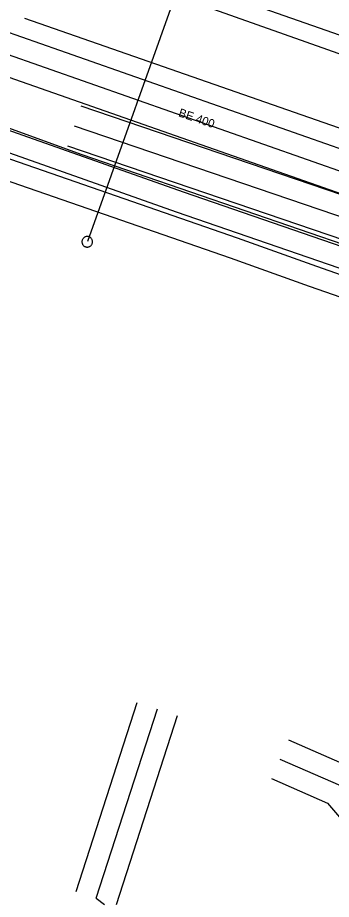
# Model space of a CAD drawing. Extents: x -762993 to -761845, y -975230 to -974501.
# Drawn here: x -762374.19 to -762359.36, y -975003.77 to -974962.16 of the extents above; entities that cross this region are included whole.
import ezdxf

# ---------------------------------------------------------------- set-up
doc = ezdxf.new("R2010")
doc.units = 0
for name, color, linetype in [('IS_CETIN_OP', 7, 'Continuous'), ('IS_CETIN_podzem metalika zam', 7, 'Continuous'), ('IS_CETIN_podzem NN', 7, 'Continuous'), ('IS_CETIN_podzem optika zam', 7, 'Continuous'), ('IS_CETIN_podzem out of order', 7, 'Continuous'), ('IS_CEZ-D_el vedeni NN podzem', 7, 'Continuous'), ('IS_CEZ-D_el vedeni VN podzem', 7, 'Continuous'), ('IS_CEZ-D_OP', 7, 'Continuous'), ('IS_DPmUL_OP', 7, 'Continuous'), ('IS_DPmUL_VO vedeni podzem', 7, 'Continuous'), ('IS_GASNET_plyn NTL rad', 7, 'Continuous'), ('IS_GASNET_plyn OP', 7, 'Continuous'), ('IS_SCVK_kanalizace anotace', 7, 'Continuous'), ('IS_SCVK_kanalizace jednotna', 7, 'Continuous'), ('IS_SCVK_vodovod OP', 7, 'Continuous'), ('IS_SCVK_vodovod pripojky', 7, 'Continuous'), ('IS_SCVK_vodovod znaky', 7, 'Continuous')]:
    doc.layers.add(name, color=color, linetype=linetype)

msp = doc.modelspace()

# ---------------------------------------------------------------- linework, layer by layer
at = {"layer": 'IS_CETIN_OP'}
for points in [[(-762361.39, -974996.234), (-762358.32, -974997.575), (-762355.772, -975000.548), (-762352.371, -975001.073), (-762342.707, -974993.089)], [(-762371.421, -975003.402), (-762368.531, -974994.472)], [(-762369.519, -975004.018), (-762366.629, -974995.088)], [(-762362.19, -974998.066), (-762359.54, -974999.225), (-762356.808, -975002.412), (-762351.789, -975003.187), (-762342.909, -974995.85)]]:
    msp.add_lwpolyline(points, dxfattribs=at)
at = {"layer": 'IS_CETIN_podzem metalika zam'}
msp.add_lwpolyline([(-762370.47, -975003.71), (-762367.58, -974994.78)], dxfattribs=at)
at = {"layer": 'IS_CETIN_podzem NN'}
msp.add_lwpolyline([(-762361.79, -974997.15), (-762358.93, -974998.4), (-762356.29, -975001.48), (-762352.08, -975002.13), (-762342.07, -974993.86)], dxfattribs=at)
at = {"layer": 'IS_CETIN_podzem optika zam'}
msp.add_lwpolyline([(-762361.79, -974997.15), (-762358.93, -974998.4), (-762356.29, -975001.48), (-762352.08, -975002.13), (-762342.07, -974993.86)], dxfattribs=at)
at = {"layer": 'IS_CETIN_podzem out of order'}
for points in [[(-762377.04, -974956.66), (-762339.91, -974969.63), (-762327.23, -974974.06)], [(-762393.36, -974970.49), (-762394.76, -974970.05), (-762391.76, -974961.27), (-762386.9, -974962.9), (-762371.15, -974968.61), (-762342.91, -974978.3), (-762324.01, -974984.93), (-762322.43, -974985.48)], [(-762370.47, -975003.71), (-762370.08, -975004.01)]]:
    msp.add_lwpolyline(points, dxfattribs=at)
at = {"layer": 'IS_CEZ-D_el vedeni NN podzem'}
msp.add_lwpolyline([(-762394.922, -974961.348), (-762366.691, -974971.325), (-762338.912, -974980.87), (-762333.235, -974982.66), (-762317.369, -974988.815), (-762313.901, -974990.502), (-762312.492, -974990.931), (-762308.55, -974979.749), (-762308.284, -974978.995), (-762308.259, -974979.004), (-762304.782, -974980.906), (-762293.136, -974984.559), (-762291.208, -974984.727), (-762288.899, -974984.279), (-762285.346, -974981.506), (-762284.881, -974980.325), (-762284.547, -974977.953), (-762290.432, -974954.683), (-762291.314, -974953.684), (-762291.816, -974954.174), (-762292.054, -974954.011)], dxfattribs=at)
at = {"layer": 'IS_CEZ-D_el vedeni VN podzem'}
msp.add_lwpolyline([(-762322.36, -974987.09), (-762324.59, -974986.24), (-762328.28, -974985.04), (-762360.05, -974973.9), (-762363.79, -974972.56), (-762395.59, -974961.56), (-762398.7, -974960.48), (-762421.28, -974952.57), (-762425.16, -974951.24), (-762434.97, -974947.57)], dxfattribs=at)
at = {"layer": 'IS_CEZ-D_OP'}
for points in [[(-762356.318, -974976.268), (-762360.384, -974974.843), (-762364.122, -974973.503), (-762395.917, -974962.505), (-762399.029, -974961.424), (-762421.607, -974953.515), (-762425.497, -974952.181), (-762435.253, -974948.532)], [(-762425.326, -974953.474), (-762425.823, -974952.392), (-762424.284, -974951.508), (-762423.951, -974951.317), (-762421.468, -974950.868), (-762394.588, -974960.405), (-762366.362, -974970.381), (-762338.599, -974979.92), (-762332.903, -974981.716), (-762317.463, -974987.706)]]:
    msp.add_lwpolyline(points, dxfattribs=at)
at = {"layer": 'IS_DPmUL_OP'}
for points in [[(-762371.192, -974966.319), (-762342.187, -974976.181)], [(-762371.836, -974968.213), (-762342.831, -974978.075)]]:
    msp.add_lwpolyline(points, dxfattribs=at)
at = {"layer": 'IS_DPmUL_VO vedeni podzem'}
msp.add_lwpolyline([(-762371.514, -974967.266), (-762342.509, -974977.128)], dxfattribs=at)
at = {"layer": 'IS_GASNET_plyn NTL rad'}
msp.add_lwpolyline([(-762416.145, -974949.855), (-762381.041, -974961.735), (-762378.19, -974962.7), (-762377.47, -974962.93), (-762377.29, -974962.99), (-762377.092, -974963.051), (-762377.03, -974963.07), (-762356.37, -974970.3), (-762354.158, -974971.062), (-762353.96, -974971.13), (-762350.61, -974972.23), (-762350.171, -974972.416), (-762350.02, -974972.48), (-762336.17, -974977.35), (-762335.29, -974977.64), (-762335.11, -974977.68), (-762305.627, -974988.849), (-762305.14, -974989.03), (-762304.73, -974989.2), (-762303.75, -974989.6), (-762303.207, -974990.005), (-762302.681, -974990.396), (-762302.34, -974990.65)], dxfattribs=at)
at = {"layer": 'IS_GASNET_plyn OP'}
for points in [[(-762376.718, -974962.12), (-762356.042, -974969.355), (-762353.833, -974970.116), (-762353.642, -974970.182), (-762350.258, -974971.293), (-762349.781, -974971.495), (-762349.659, -974971.547), (-762335.848, -974976.403), (-762335.024, -974976.675), (-762334.823, -974976.719), (-762305.276, -974987.913)], [(-762305.978, -974989.785), (-762335.397, -974978.641), (-762335.556, -974978.605), (-762336.492, -974978.297), (-762350.381, -974973.413), (-762350.561, -974973.337), (-762350.962, -974973.167), (-762354.278, -974972.078), (-762354.483, -974972.008), (-762356.698, -974971.245), (-762377.342, -974964.02)]]:
    msp.add_lwpolyline(points, dxfattribs=at)
at = {"layer": 'IS_SCVK_kanalizace jednotna'}
msp.add_lwpolyline([(-762373.865, -974962.18), (-762330.791, -974977.171)], dxfattribs=at)
at = {"layer": 'IS_SCVK_vodovod OP'}
msp.add_lwpolyline([(-762371.852, -974959.319), (-762366.733, -974961.125), (-762365.959, -974961.392), (-762351.074, -974966.651), (-762348.097, -974967.643), (-762328.082, -974974.681), (-762324.702, -974975.757), (-762322.277, -974976.604), (-762303.577, -974983.171), (-762292.841, -974986.577), (-762286.645, -974987.706), (-762284.209, -974987.979), (-762282.49, -974987.47)], dxfattribs=at)
at = {"layer": 'IS_SCVK_vodovod pripojky'}
msp.add_lwpolyline([(-762366.338, -974959.969), (-762370.882, -974972.729)], dxfattribs=at)
at = {"layer": 'IS_SCVK_vodovod znaky'}
for points in [[(-762371.145, -974972.707), (-762371.147, -974972.733)], [(-762371.145, -974972.707), (-762371.147, -974972.733)], [(-762371.147, -974972.733), (-762371.145, -974972.758)], [(-762371.147, -974972.733), (-762371.145, -974972.758)], [(-762371.145, -974972.758), (-762371.142, -974972.784)], [(-762371.145, -974972.758), (-762371.142, -974972.784)], [(-762371.14, -974972.681), (-762371.145, -974972.707)], [(-762371.14, -974972.681), (-762371.145, -974972.707)], [(-762371.142, -974972.784), (-762371.135, -974972.81)], [(-762371.142, -974972.784), (-762371.135, -974972.81)], [(-762371.133, -974972.655), (-762371.14, -974972.681)], [(-762371.133, -974972.655), (-762371.14, -974972.681)], [(-762371.135, -974972.81), (-762371.126, -974972.834)], [(-762371.135, -974972.81), (-762371.126, -974972.834)], [(-762371.123, -974972.632), (-762371.133, -974972.655)], [(-762371.123, -974972.632), (-762371.133, -974972.655)], [(-762371.126, -974972.834), (-762371.115, -974972.858)], [(-762371.126, -974972.834), (-762371.115, -974972.858)], [(-762371.111, -974972.608), (-762371.123, -974972.632)], [(-762371.111, -974972.608), (-762371.123, -974972.632)], [(-762371.115, -974972.858), (-762371.101, -974972.88)], [(-762371.115, -974972.858), (-762371.101, -974972.88)], [(-762371.096, -974972.586), (-762371.111, -974972.608)], [(-762371.096, -974972.586), (-762371.111, -974972.608)], [(-762371.101, -974972.88), (-762371.084, -974972.9)], [(-762371.101, -974972.88), (-762371.084, -974972.9)], [(-762371.08, -974972.567), (-762371.096, -974972.586)], [(-762371.08, -974972.567), (-762371.096, -974972.586)], [(-762371.062, -974972.548), (-762371.08, -974972.567)], [(-762371.062, -974972.548), (-762371.08, -974972.567)], [(-762371.042, -974972.532), (-762371.062, -974972.548)], [(-762371.042, -974972.532), (-762371.062, -974972.548)], [(-762371.019, -974972.518), (-762371.042, -974972.532)], [(-762371.019, -974972.518), (-762371.042, -974972.532)], [(-762370.996, -974972.506), (-762371.019, -974972.518)], [(-762370.996, -974972.506), (-762371.019, -974972.518)], [(-762370.971, -974972.498), (-762370.996, -974972.506)], [(-762370.971, -974972.498), (-762370.996, -974972.506)], [(-762370.945, -974972.49), (-762370.971, -974972.498)], [(-762370.945, -974972.49), (-762370.971, -974972.498)], [(-762370.919, -974972.486), (-762370.945, -974972.49)], [(-762370.919, -974972.486), (-762370.945, -974972.49)], [(-762370.894, -974972.486), (-762370.919, -974972.486)], [(-762370.894, -974972.486), (-762370.919, -974972.486)], [(-762370.867, -974972.488), (-762370.894, -974972.486)], [(-762370.867, -974972.488), (-762370.894, -974972.486)], [(-762370.842, -974972.492), (-762370.867, -974972.488)], [(-762370.842, -974972.492), (-762370.867, -974972.488)], [(-762370.816, -974972.499), (-762370.842, -974972.492)], [(-762370.816, -974972.499), (-762370.842, -974972.492)], [(-762370.792, -974972.509), (-762370.816, -974972.499)], [(-762370.792, -974972.509), (-762370.816, -974972.499)], [(-762370.769, -974972.521), (-762370.792, -974972.509)], [(-762370.769, -974972.521), (-762370.792, -974972.509)], [(-762370.748, -974972.535), (-762370.769, -974972.521)], [(-762370.748, -974972.535), (-762370.769, -974972.521)], [(-762370.727, -974972.552), (-762370.748, -974972.535)], [(-762370.727, -974972.552), (-762370.748, -974972.535)], [(-762370.709, -974972.571), (-762370.727, -974972.552)], [(-762370.709, -974972.571), (-762370.727, -974972.552)], [(-762370.693, -974972.592), (-762370.709, -974972.571)], [(-762370.693, -974972.592), (-762370.709, -974972.571)], [(-762370.696, -974972.885), (-762370.682, -974972.863)], [(-762370.696, -974972.885), (-762370.682, -974972.863)], [(-762370.679, -974972.614), (-762370.693, -974972.592)], [(-762370.679, -974972.614), (-762370.693, -974972.592)], [(-762370.682, -974972.863), (-762370.67, -974972.84)], [(-762370.682, -974972.863), (-762370.67, -974972.84)], [(-762370.667, -974972.637), (-762370.679, -974972.614)], [(-762370.667, -974972.637), (-762370.679, -974972.614)], [(-762370.67, -974972.84), (-762370.66, -974972.816)], [(-762370.67, -974972.84), (-762370.66, -974972.816)], [(-762370.659, -974972.662), (-762370.667, -974972.637)], [(-762370.659, -974972.662), (-762370.667, -974972.637)], [(-762370.66, -974972.816), (-762370.653, -974972.791)], [(-762370.66, -974972.816), (-762370.653, -974972.791)], [(-762370.652, -974972.687), (-762370.659, -974972.662)], [(-762370.652, -974972.687), (-762370.659, -974972.662)], [(-762370.653, -974972.791), (-762370.648, -974972.765)], [(-762370.653, -974972.791), (-762370.648, -974972.765)], [(-762370.648, -974972.713), (-762370.652, -974972.687)], [(-762370.648, -974972.713), (-762370.652, -974972.687)], [(-762370.647, -974972.739), (-762370.648, -974972.713)], [(-762370.647, -974972.739), (-762370.648, -974972.713)], [(-762370.648, -974972.765), (-762370.647, -974972.739)], [(-762370.648, -974972.765), (-762370.647, -974972.739)], [(-762371.084, -974972.9), (-762371.066, -974972.92)], [(-762371.084, -974972.9), (-762371.066, -974972.92)], [(-762371.066, -974972.92), (-762371.047, -974972.936)], [(-762371.066, -974972.92), (-762371.047, -974972.936)], [(-762371.047, -974972.936), (-762371.024, -974972.951)], [(-762371.047, -974972.936), (-762371.024, -974972.951)], [(-762371.024, -974972.951), (-762371.001, -974972.962)], [(-762371.024, -974972.951), (-762371.001, -974972.962)], [(-762371.001, -974972.962), (-762370.977, -974972.973)], [(-762371.001, -974972.962), (-762370.977, -974972.973)], [(-762370.977, -974972.973), (-762370.952, -974972.979)], [(-762370.977, -974972.973), (-762370.952, -974972.979)], [(-762370.952, -974972.979), (-762370.926, -974972.984)], [(-762370.952, -974972.979), (-762370.926, -974972.984)], [(-762370.926, -974972.984), (-762370.9, -974972.986)], [(-762370.926, -974972.984), (-762370.9, -974972.986)], [(-762370.9, -974972.986), (-762370.873, -974972.984)], [(-762370.9, -974972.986), (-762370.873, -974972.984)], [(-762370.873, -974972.984), (-762370.848, -974972.981)], [(-762370.873, -974972.984), (-762370.848, -974972.981)], [(-762370.848, -974972.981), (-762370.823, -974972.975)], [(-762370.848, -974972.981), (-762370.823, -974972.975)], [(-762370.823, -974972.975), (-762370.797, -974972.965)], [(-762370.823, -974972.975), (-762370.797, -974972.965)], [(-762370.797, -974972.965), (-762370.775, -974972.954)], [(-762370.797, -974972.965), (-762370.775, -974972.954)], [(-762370.775, -974972.954), (-762370.753, -974972.94)], [(-762370.775, -974972.954), (-762370.753, -974972.94)], [(-762370.753, -974972.94), (-762370.731, -974972.924)], [(-762370.753, -974972.94), (-762370.731, -974972.924)], [(-762370.731, -974972.924), (-762370.713, -974972.905)], [(-762370.731, -974972.924), (-762370.713, -974972.905)], [(-762370.713, -974972.905), (-762370.696, -974972.885)], [(-762370.713, -974972.905), (-762370.696, -974972.885)]]:
    msp.add_lwpolyline(points, dxfattribs=at)

# ---------------------------------------------------------------- texts
at = {"layer": 'IS_SCVK_kanalizace anotace'}
msp.add_text('BE 400', height=0.4, rotation=341, dxfattribs=at).set_placement((-762366.617, -974966.805))

doc.saveas('drawing.dxf')
